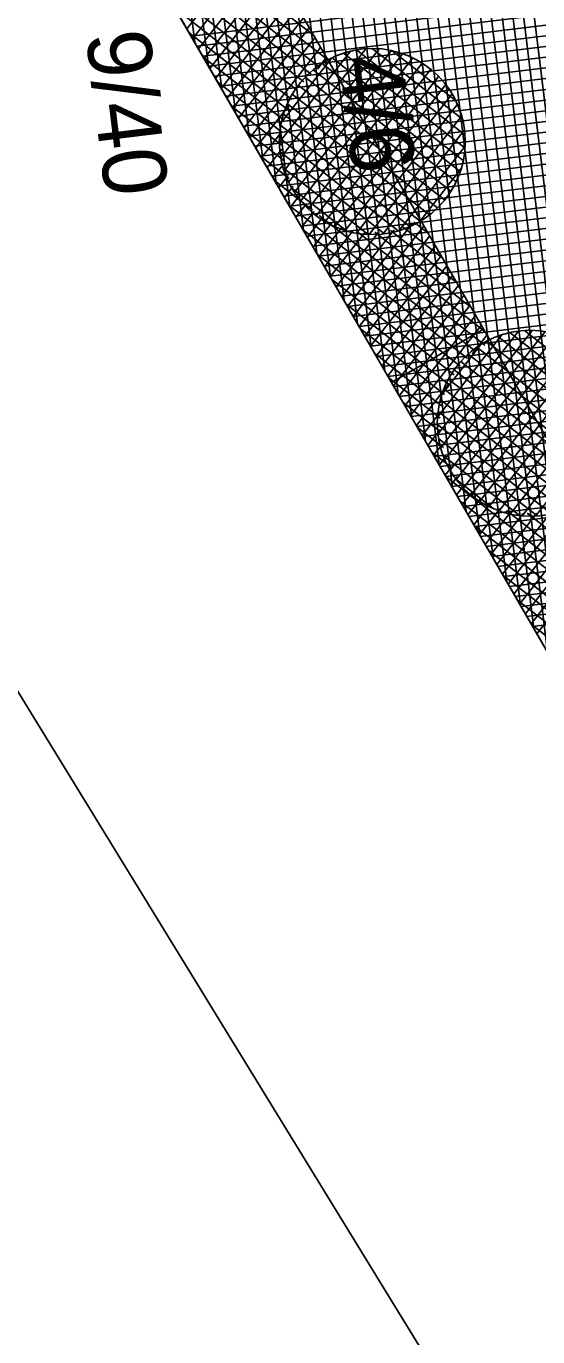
# Model space of a CAD drawing. Extents: x -566982 to -566809, y -1095912 to -1095685.
# Drawn here: x -566942.23 to -566932.6, y -1095771.05 to -1095746.4 of the extents above; entities that cross this region are included whole.
import ezdxf

# ---------------------------------------------------------------- set-up
doc = ezdxf.new("R2010")
doc.units = 0
for name, color, linetype in [('Vrstva 1', 7, 'Continuous'), ('Vrstva 40', 7, 'Continuous'), ('Vrstva 41', 7, 'Continuous'), ('Vrstva 42', 7, 'Continuous'), ('Vrstva 43', 7, 'Continuous'), ('Vrstva 44', 7, 'Continuous')]:
    doc.layers.add(name, color=color, linetype=linetype)

msp = doc.modelspace()

# ---------------------------------------------------------------- linework, layer by layer
at = {"layer": 'Vrstva 1'}
for p, q in [((-566956.66, -1095716.28), (-566892.27, -1095827.53)), ((-566954.26, -1095739.57), (-566928.71, -1095781.18))]:
    msp.add_line(p, q, dxfattribs=at)
at = {"layer": 'Vrstva 41'}
for p, q in [((-566940.237, -1095744.655), (-566936.86, -1095747.298)), ((-566939.968, -1095745.12), (-566937.001, -1095747.441)), ((-566939.173, -1095745.234), (-566936.699, -1095747.17)), ((-566937.947, -1095745.169), (-566939.092, -1095746.632)), ((-566937.656, -1095745.121), (-566938.984, -1095746.819)), ((-566938.287, -1095745.279), (-566939.2, -1095746.446)), ((-566937.548, -1095745.308), (-566938.877, -1095747.005)), ((-566937.44, -1095745.494), (-566938.769, -1095747.192)), ((-566938.751, -1095745.31), (-566936.55, -1095747.032)), ((-566938.433, -1095745.305), (-566936.819, -1095746.568)), ((-566939.699, -1095745.584), (-566937.123, -1095747.6)), ((-566937.332, -1095745.681), (-566938.661, -1095747.379)), ((-566937.224, -1095745.867), (-566938.553, -1095747.565)), ((-566939.431, -1095746.048), (-566937.226, -1095747.773)), ((-566937.116, -1095746.054), (-566938.445, -1095747.752)), ((-566937.008, -1095746.241), (-566938.337, -1095747.938)), ((-566936.9, -1095746.427), (-566938.229, -1095748.125)), ((-566939.162, -1095746.512), (-566937.31, -1095747.961)), ((-566936.792, -1095746.614), (-566938.121, -1095748.311)), ((-566938.893, -1095746.976), (-566937.373, -1095748.166)), ((-566936.684, -1095746.8), (-566938.013, -1095748.498)), ((-566936.576, -1095746.987), (-566936.745, -1095747.202)), ((-566938.625, -1095747.44), (-566937.412, -1095748.389)), ((-566938.356, -1095747.905), (-566937.42, -1095748.637)), ((-566937.283, -1095747.89), (-566937.905, -1095748.684)), ((-566938.087, -1095748.369), (-566937.384, -1095748.919)), ((-566937.411, -1095748.378), (-566937.797, -1095748.871)), ((-566937.415, -1095748.707), (-566937.689, -1095749.058)), ((-566937.819, -1095748.833), (-566937.275, -1095749.259)), ((-566937.371, -1095748.977), (-566937.581, -1095749.244)), ((-566937.296, -1095749.205), (-566937.473, -1095749.431)), ((-566937.55, -1095749.297), (-566936.837, -1095749.855)), ((-566937.2, -1095749.407), (-566937.365, -1095749.617)), ((-566937.086, -1095749.585), (-566937.257, -1095749.804)), ((-566937.281, -1095749.761), (-566933.767, -1095752.511)), ((-566936.955, -1095749.742), (-566937.149, -1095749.99)), ((-566936.807, -1095749.879), (-566937.041, -1095750.177)), ((-566936.646, -1095749.997), (-566936.933, -1095750.363)), ((-566936.471, -1095750.097), (-566936.825, -1095750.55)), ((-566936.28, -1095750.178), (-566936.717, -1095750.737)), ((-566936.711, -1095749.954), (-566933.591, -1095752.395)), ((-566934.945, -1095750.095), (-566936.177, -1095751.669)), ((-566934.741, -1095750.158), (-566936.069, -1095751.856)), ((-566935.13, -1095750.175), (-566934.401, -1095750.746)), ((-566934.923, -1095750.083), (-566934.669, -1095750.282)), ((-566937.013, -1095750.225), (-566933.921, -1095752.645)), ((-566936.073, -1095750.238), (-566936.609, -1095750.923)), ((-566935.845, -1095750.271), (-566936.501, -1095751.11)), ((-566935.587, -1095750.266), (-566936.393, -1095751.296)), ((-566935.302, -1095750.227), (-566936.285, -1095751.483)), ((-566936.007, -1095750.25), (-566933.595, -1095752.138)), ((-566934.633, -1095750.345), (-566935.961, -1095752.042)), ((-566935.661, -1095750.268), (-566933.863, -1095751.674)), ((-566935.37, -1095750.241), (-566934.132, -1095751.21)), ((-566934.525, -1095750.531), (-566935.853, -1095752.229)), ((-566936.744, -1095750.69), (-566934.056, -1095752.793)), ((-566934.417, -1095750.718), (-566935.745, -1095752.416)), ((-566934.309, -1095750.904), (-566935.637, -1095752.602)), ((-566936.476, -1095751.154), (-566934.173, -1095752.956)), ((-566934.201, -1095751.091), (-566935.529, -1095752.789)), ((-566934.093, -1095751.278), (-566935.421, -1095752.975)), ((-566936.207, -1095751.618), (-566934.271, -1095753.133)), ((-566933.985, -1095751.464), (-566935.313, -1095753.162)), ((-566933.877, -1095751.651), (-566935.205, -1095753.348)), ((-566933.769, -1095751.837), (-566935.097, -1095753.535)), ((-566935.938, -1095752.082), (-566934.349, -1095753.326)), ((-566933.661, -1095752.024), (-566934.989, -1095753.721)), ((-566933.553, -1095752.21), (-566933.829, -1095752.563)), ((-566935.67, -1095752.546), (-566934.406, -1095753.535)), ((-566935.401, -1095753.01), (-566934.434, -1095753.767)), ((-566934.264, -1095753.119), (-566934.881, -1095753.908)), ((-566935.132, -1095753.475), (-566934.429, -1095754.025)), ((-566934.422, -1095753.646), (-566934.773, -1095754.095)), ((-566934.864, -1095753.939), (-566934.373, -1095754.322)), ((-566934.432, -1095753.983), (-566934.665, -1095754.281)), ((-566934.392, -1095754.257), (-566934.557, -1095754.468)), ((-566934.595, -1095754.403), (-566934.219, -1095754.697)), ((-566934.318, -1095754.487), (-566934.45, -1095754.654)), ((-566934.223, -1095754.689), (-566934.342, -1095754.841)), ((-566934.326, -1095754.867), (-566931.16, -1095757.345)), ((-566934.11, -1095754.869), (-566934.234, -1095755.027)), ((-566933.98, -1095755.027), (-566934.126, -1095755.214)), ((-566934.058, -1095755.331), (-566931.31, -1095757.482)), ((-566933.833, -1095755.164), (-566934.018, -1095755.4)), ((-566933.673, -1095755.284), (-566933.91, -1095755.587)), ((-566933.498, -1095755.385), (-566933.802, -1095755.774)), ((-566933.307, -1095755.466), (-566933.694, -1095755.96)), ((-566933.1, -1095755.526), (-566933.586, -1095756.147)), ((-566932.873, -1095755.56), (-566933.478, -1095756.333)), ((-566932.615, -1095755.555), (-566933.37, -1095756.52)), ((-566932.33, -1095755.516), (-566933.262, -1095756.706)), ((-566933.188, -1095755.504), (-566930.991, -1095757.223)), ((-566931.972, -1095755.383), (-566933.154, -1095756.893)), ((-566931.717, -1095755.382), (-566933.046, -1095757.079)), ((-566931.609, -1095755.568), (-566932.938, -1095757.266)), ((-566932.794, -1095755.558), (-566930.798, -1095757.12)), ((-566933.789, -1095755.795), (-566931.44, -1095757.633)), ((-566931.501, -1095755.755), (-566932.83, -1095757.453)), ((-566931.393, -1095755.941), (-566932.722, -1095757.639)), ((-566933.52, -1095756.26), (-566931.553, -1095757.799)), ((-566931.286, -1095756.128), (-566932.614, -1095757.826)), ((-566933.252, -1095756.724), (-566931.647, -1095757.98)), ((-566932.983, -1095757.188), (-566931.719, -1095758.177)), ((-566932.714, -1095757.652), (-566931.767, -1095758.394))]:
    msp.add_line(p, q, dxfattribs=at)
at = {"layer": 'Vrstva 42'}
msp.add_line((-566935.35, -1095753.098), (-566933.619, -1095752.096), dxfattribs=at)
msp.add_lwpolyline([(-566834.15, -1095760.69), (-566836.072, -1095760.136), (-566841.286, -1095779.189), (-566855.268, -1095796.126), (-566881.984, -1095814.851), (-566891.818, -1095824.318), (-566954.342, -1095716.292), (-566956.66, -1095716.28), (-566892.27, -1095827.53), (-566880.71, -1095816.4), (-566853.9, -1095797.61), (-566839.47, -1095780.13)], close=True, dxfattribs=at)
at = {"layer": 'Vrstva 43'}
for p, q in [((-566942.138, -1095721.406), (-566939.051, -1095746.704)), ((-566941.883, -1095721.847), (-566938.796, -1095747.145)), ((-566941.628, -1095722.288), (-566938.54, -1095747.586)), ((-566941.372, -1095722.729), (-566938.285, -1095748.027)), ((-566941.117, -1095723.17), (-566938.03, -1095748.469)), ((-566940.862, -1095723.611), (-566937.774, -1095748.91)), ((-566940.606, -1095724.052), (-566937.519, -1095749.351)), ((-566940.351, -1095724.493), (-566937.264, -1095749.792)), ((-566940.096, -1095724.934), (-566937.008, -1095750.233)), ((-566939.84, -1095725.376), (-566936.753, -1095750.674)), ((-566939.585, -1095725.817), (-566936.498, -1095751.115)), ((-566939.33, -1095726.258), (-566936.242, -1095751.556)), ((-566939.074, -1095726.699), (-566935.987, -1095751.998)), ((-566938.819, -1095727.14), (-566935.732, -1095752.439)), ((-566938.564, -1095727.581), (-566935.477, -1095752.88)), ((-566938.308, -1095728.022), (-566935.221, -1095753.321)), ((-566938.053, -1095728.463), (-566934.966, -1095753.762)), ((-566937.798, -1095728.905), (-566934.711, -1095754.203)), ((-566937.542, -1095729.346), (-566934.455, -1095754.644)), ((-566937.287, -1095729.787), (-566934.2, -1095755.085)), ((-566937.032, -1095730.228), (-566933.945, -1095755.526)), ((-566936.777, -1095730.669), (-566933.689, -1095755.968)), ((-566936.521, -1095731.11), (-566933.434, -1095756.409)), ((-566936.266, -1095731.551), (-566933.179, -1095756.85)), ((-566936.011, -1095731.992), (-566932.923, -1095757.291)), ((-566935.755, -1095732.433), (-566932.668, -1095757.732)), ((-566935.5, -1095732.875), (-566932.413, -1095758.173)), ((-566935.245, -1095733.316), (-566932.157, -1095758.614)), ((-566934.989, -1095733.757), (-566931.902, -1095759.055)), ((-566934.734, -1095734.198), (-566931.647, -1095759.497)), ((-566934.479, -1095734.639), (-566931.392, -1095759.938)), ((-566934.223, -1095735.08), (-566931.136, -1095760.379)), ((-566933.968, -1095735.521), (-566930.881, -1095760.82)), ((-566939.12, -1095746.584), (-566928.327, -1095745.267)), ((-566939.011, -1095746.773), (-566928.218, -1095745.456)), ((-566938.902, -1095746.961), (-566928.109, -1095745.644)), ((-566938.793, -1095747.149), (-566928, -1095745.832)), ((-566938.684, -1095747.337), (-566927.892, -1095746.02)), ((-566938.576, -1095747.525), (-566927.783, -1095746.208)), ((-566938.467, -1095747.714), (-566927.674, -1095746.397)), ((-566938.358, -1095747.902), (-566927.565, -1095746.585)), ((-566938.249, -1095748.09), (-566927.456, -1095746.773)), ((-566938.14, -1095748.278), (-566927.347, -1095746.961)), ((-566938.031, -1095748.466), (-566927.238, -1095747.149)), ((-566937.922, -1095748.655), (-566927.129, -1095747.338)), ((-566937.813, -1095748.843), (-566927.02, -1095747.526)), ((-566937.704, -1095749.031), (-566926.911, -1095747.714)), ((-566937.595, -1095749.219), (-566926.802, -1095747.902)), ((-566937.486, -1095749.407), (-566926.693, -1095748.09)), ((-566937.377, -1095749.596), (-566926.584, -1095748.278)), ((-566937.268, -1095749.784), (-566926.476, -1095748.467)), ((-566937.16, -1095749.972), (-566926.367, -1095748.655)), ((-566937.051, -1095750.16), (-566926.258, -1095748.843)), ((-566936.942, -1095750.348), (-566926.149, -1095749.031)), ((-566936.833, -1095750.536), (-566926.04, -1095749.219)), ((-566936.724, -1095750.725), (-566925.931, -1095749.408)), ((-566936.615, -1095750.913), (-566925.822, -1095749.596)), ((-566936.506, -1095751.101), (-566925.713, -1095749.784)), ((-566936.397, -1095751.289), (-566925.604, -1095749.972)), ((-566936.288, -1095751.477), (-566925.495, -1095750.16)), ((-566936.179, -1095751.666), (-566925.386, -1095750.349)), ((-566936.07, -1095751.854), (-566925.277, -1095750.537)), ((-566935.961, -1095752.042), (-566925.168, -1095750.725)), ((-566935.852, -1095752.23), (-566925.06, -1095750.913)), ((-566935.744, -1095752.418), (-566924.951, -1095751.101)), ((-566935.635, -1095752.607), (-566924.842, -1095751.29)), ((-566935.526, -1095752.795), (-566924.733, -1095751.478)), ((-566935.417, -1095752.983), (-566924.624, -1095751.666)), ((-566935.308, -1095753.171), (-566924.515, -1095751.854)), ((-566935.199, -1095753.359), (-566924.406, -1095752.042)), ((-566935.09, -1095753.548), (-566924.297, -1095752.23)), ((-566934.981, -1095753.736), (-566924.188, -1095752.419)), ((-566934.872, -1095753.924), (-566924.079, -1095752.607)), ((-566934.763, -1095754.112), (-566923.97, -1095752.795)), ((-566934.654, -1095754.3), (-566923.861, -1095752.983)), ((-566934.545, -1095754.489), (-566923.752, -1095753.171)), ((-566934.436, -1095754.677), (-566923.644, -1095753.36)), ((-566934.328, -1095754.865), (-566923.535, -1095753.548)), ((-566934.219, -1095755.053), (-566923.426, -1095753.736)), ((-566934.11, -1095755.241), (-566923.317, -1095753.924)), ((-566934.001, -1095755.429), (-566923.208, -1095754.112)), ((-566933.892, -1095755.618), (-566923.099, -1095754.301)), ((-566933.783, -1095755.806), (-566922.99, -1095754.489)), ((-566933.674, -1095755.994), (-566922.881, -1095754.677)), ((-566933.565, -1095756.182), (-566922.772, -1095754.865)), ((-566933.456, -1095756.37), (-566922.663, -1095755.053)), ((-566933.347, -1095756.559), (-566922.554, -1095755.242)), ((-566933.238, -1095756.747), (-566922.445, -1095755.43)), ((-566933.129, -1095756.935), (-566922.336, -1095755.618)), ((-566933.021, -1095757.123), (-566922.228, -1095755.806)), ((-566932.912, -1095757.311), (-566922.119, -1095755.994)), ((-566932.803, -1095757.5), (-566922.01, -1095756.183)), ((-566932.694, -1095757.688), (-566921.901, -1095756.371))]:
    msp.add_line(p, q, dxfattribs=at)
msp.add_lwpolyline([(-566834.15, -1095760.69), (-566843.76, -1095757.92), (-566848.55, -1095775.42), (-566860.75, -1095790.2), (-566887.09, -1095808.66), (-566890.01, -1095811.47), (-566945.07, -1095716.34), (-566956.66, -1095716.28), (-566892.27, -1095827.53), (-566880.71, -1095816.4), (-566853.9, -1095797.61), (-566839.47, -1095780.13)], close=True, dxfattribs=at)
at = {"layer": 'Vrstva 44'}
for p, q in [((-566936.121, -1095746.867), (-566937.459, -1095748.576)), ((-566935.832, -1095746.821), (-566937.433, -1095748.867)), ((-566935.579, -1095746.823), (-566937.372, -1095749.114)), ((-566935.349, -1095746.854), (-566937.285, -1095749.327)), ((-566935.142, -1095746.913), (-566937.178, -1095749.516)), ((-566936.467, -1095746.989), (-566933.999, -1095748.921)), ((-566936.252, -1095746.904), (-566933.966, -1095748.693)), ((-566936.007, -1095746.842), (-566933.968, -1095748.437)), ((-566935.713, -1095746.817), (-566934.013, -1095748.148)), ((-566935.338, -1095746.857), (-566934.144, -1095747.791)), ((-566936.473, -1095746.992), (-566937.421, -1095748.203)), ((-566934.95, -1095746.992), (-566937.056, -1095749.684)), ((-566934.773, -1095747.09), (-566936.918, -1095749.832)), ((-566936.824, -1095747.218), (-566934.133, -1095749.323)), ((-566934.609, -1095747.206), (-566936.765, -1095749.961)), ((-566936.657, -1095747.095), (-566934.056, -1095749.13)), ((-566936.972, -1095747.356), (-566934.232, -1095749.5)), ((-566934.462, -1095747.342), (-566936.598, -1095750.072)), ((-566937.216, -1095747.673), (-566934.484, -1095749.811)), ((-566937.103, -1095747.508), (-566934.349, -1095749.662)), ((-566934.328, -1095747.496), (-566936.417, -1095750.165)), ((-566934.21, -1095747.67), (-566936.221, -1095750.239)), ((-566937.308, -1095747.855), (-566934.636, -1095749.946)), ((-566934.108, -1095747.864), (-566936.006, -1095750.289)), ((-566937.381, -1095748.052), (-566934.808, -1095750.065)), ((-566934.029, -1095748.088), (-566935.772, -1095750.315)), ((-566937.433, -1095748.265), (-566935.005, -1095750.165)), ((-566933.975, -1095748.344), (-566935.508, -1095750.302)), ((-566937.458, -1095748.499), (-566935.226, -1095750.246)), ((-566933.964, -1095748.654), (-566935.205, -1095750.239)), ((-566937.448, -1095748.761), (-566935.482, -1095750.299)), ((-566937.387, -1095749.063), (-566935.789, -1095750.313)), ((-566934.037, -1095749.072), (-566934.819, -1095750.071)), ((-566937.223, -1095749.445), (-566936.199, -1095750.246)), ((-566932.962, -1095752.131), (-566934.474, -1095754.064)), ((-566932.696, -1095752.116), (-566934.424, -1095754.324)), ((-566932.46, -1095752.139), (-566934.346, -1095754.549)), ((-566933.121, -1095752.16), (-566930.988, -1095753.829)), ((-566932.848, -1095752.12), (-566931.017, -1095753.552)), ((-566933.27, -1095752.2), (-566934.482, -1095753.75)), ((-566933.666, -1095752.382), (-566934.397, -1095753.317)), ((-566932.244, -1095752.187), (-566934.247, -1095754.748)), ((-566932.045, -1095752.258), (-566934.13, -1095754.922)), ((-566931.864, -1095752.35), (-566933.997, -1095755.077)), ((-566933.561, -1095752.323), (-566931.042, -1095754.295)), ((-566933.357, -1095752.229), (-566931.001, -1095754.072)), ((-566933.904, -1095752.563), (-566931.193, -1095754.684)), ((-566931.696, -1095752.461), (-566933.85, -1095755.214)), ((-566933.743, -1095752.435), (-566931.107, -1095754.498)), ((-566931.542, -1095752.589), (-566933.689, -1095755.333)), ((-566934.17, -1095752.863), (-566931.42, -1095755.015)), ((-566934.047, -1095752.705), (-566931.297, -1095754.856)), ((-566931.402, -1095752.734), (-566933.513, -1095755.432)), ((-566931.278, -1095752.9), (-566933.322, -1095755.512)), ((-566934.275, -1095753.034), (-566931.559, -1095755.159)), ((-566931.171, -1095753.088), (-566933.116, -1095755.573)), ((-566934.362, -1095753.22), (-566931.72, -1095755.287)), ((-566931.082, -1095753.299), (-566932.888, -1095755.606)), ((-566934.471, -1095753.642), (-566932.104, -1095755.495)), ((-566934.429, -1095753.422), (-566931.901, -1095755.4)), ((-566931.019, -1095753.542), (-566932.638, -1095755.611)), ((-566934.485, -1095753.886), (-566932.337, -1095755.567)), ((-566934.46, -1095754.159), (-566932.607, -1095755.609)), ((-566934.373, -1095754.481), (-566932.94, -1095755.602)), ((-566934.121, -1095754.932), (-566933.439, -1095755.466))]:
    msp.add_line(p, q, dxfattribs=at)
for centre in [(-566935.711, -1095748.566), (-566932.737, -1095753.865)]:
    msp.add_circle(centre, 1.75, dxfattribs=at)

# ---------------------------------------------------------------- texts
at = {"layer": 'Vrstva 40'}
for s, p in [('9/40', (-566941.105, -1095746.545)), ('4/6', (-566936.345, -1095747.001))]:
    msp.add_text(s, height=1.2, rotation=276.9575, dxfattribs=at).set_placement(p)

doc.saveas('drawing.dxf')
